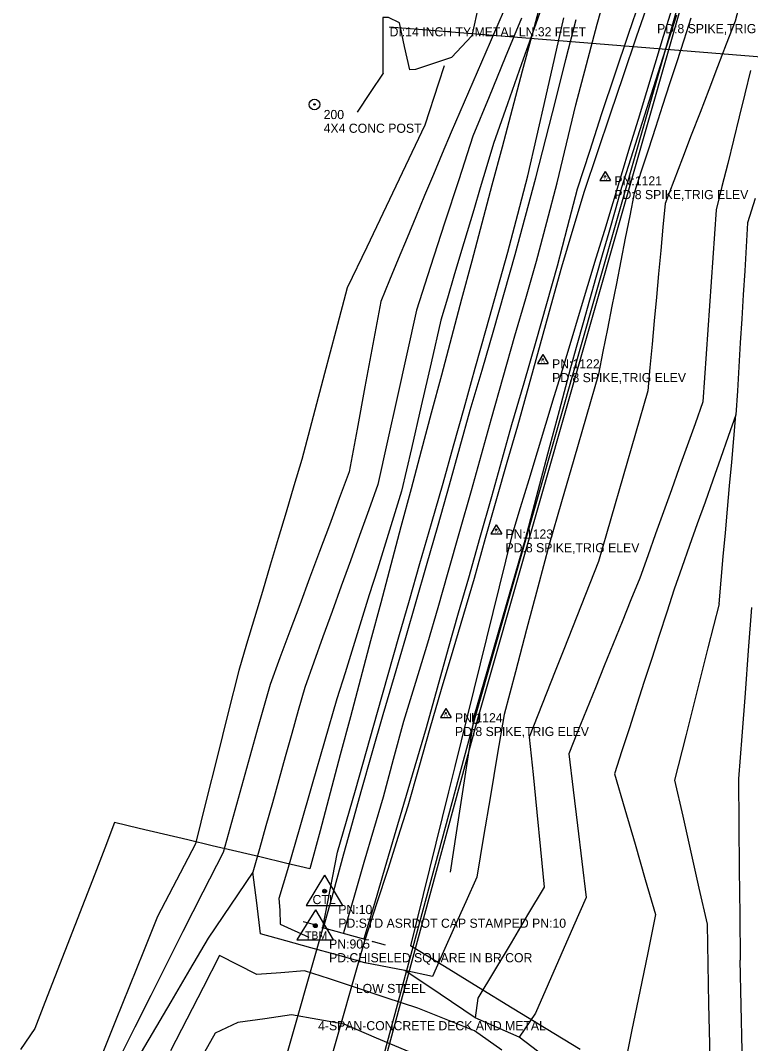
# Model space of a CAD drawing. Extents: x 1445297 to 1476720, y 2042269 to 2057889.
# Drawn here: x 1445937 to 1446336, y 2055534 to 2056093 of the extents above; entities that cross this region are included whole.
import ezdxf

# ---------------------------------------------------------------- set-up
doc = ezdxf.new("R2010")
doc.units = 0
for name, color, linetype in [('S_BRIDGE', 7, 'Continuous'), ('S_DITCHLINE', 7, 'Continuous'), ('S_DRG_PT_SYM', 7, 'Continuous'), ('S_EDGE_PAVEMENT', 7, 'Continuous'), ('S_FIBER_OPTIC_CABLE', 7, 'Continuous'), ('S_IRON_PIN', 7, 'Continuous'), ('S_IRON_PIN_ANNOT', 7, 'Continuous'), ('S_MSC_PT_SYM', 7, 'Continuous'), ('S_PAVEMENT_CROWN', 7, 'Continuous'), ('S_PRIMARY_CTL', 7, 'Continuous'), ('S_PRIMARY_CTL_ANNOT', 7, 'Continuous'), ('S_SECONDARY_CTL', 7, 'Continuous'), ('S_SECONDARY_CTL_ANNOT', 7, 'Continuous'), ('S_SHOULDER', 7, 'Continuous'), ('S_SIDE_DRAIN', 7, 'Continuous'), ('S_SIDE_DRAIN_ANNOT', 7, 'Continuous'), ('S_STR_PT_SYM', 7, 'Continuous'), ('S_STREAM', 7, 'Continuous'), ('S_SURVEY_TEXT_ANNOT', 7, 'Continuous'), ('S_TREE', 7, 'Continuous'), ('S_UNDERGROUND_CABLE', 7, 'Continuous'), ('S_UTL_PT_SYM', 7, 'Continuous'), ('S_WALL', 7, 'Continuous')]:
    doc.layers.add(name, color=color, linetype=linetype)

msp = doc.modelspace()

# ---------------------------------------------------------------- linework, layer by layer
at = {"layer": 'S_BRIDGE'}
for p, q in [((1446101.76, 2055597.5), (1446074.53, 2055501.41)), ((1446124.93, 2055591.15), (1446101.76, 2055597.5)), ((1446097.53, 2055494.89), (1446124.93, 2055591.15))]:
    msp.add_line(p, q, dxfattribs=at)
at = {"layer": 'S_DITCHLINE'}
for points in [[(1446332.26, 2056112.65), (1446327.11, 2056093), (1446322.32, 2056080.54), (1446317.54, 2056068.07), (1446312.75, 2056055.61), (1446307.96, 2056043.15), (1446303.18, 2056030.69), (1446298.39, 2056018.23), (1446293.6, 2056005.77), (1446288.82, 2055993.31), (1446287.64, 2055980.52), (1446286.46, 2055967.72), (1446285.28, 2055954.93), (1446284.1, 2055942.14), (1446282.92, 2055929.34), (1446281.74, 2055916.55), (1446280.56, 2055903.76), (1446279.39, 2055890.96), (1446272.64, 2055867.62), (1446265.9, 2055844.29), (1446259.16, 2055820.95), (1446252.41, 2055797.61), (1446247.69, 2055785.62), (1446242.97, 2055773.63), (1446238.25, 2055761.64), (1446233.53, 2055749.65), (1446228.81, 2055737.67), (1446224.09, 2055725.68), (1446219.37, 2055713.69), (1446214.65, 2055701.7), (1446216.68, 2055681.19), (1446218.71, 2055660.69), (1446220.74, 2055640.18), (1446222.77, 2055619.68), (1446213.71, 2055604.49), (1446204.66, 2055589.31), (1446195.61, 2055574.13), (1446186.56, 2055558.95), (1446185.11, 2055548.2)], [(1446200.32, 2056097.96), (1446190.83, 2056076.09), (1446181.35, 2056054.22), (1446171.87, 2056032.35), (1446167.07, 2056020.79), (1446162.27, 2056009.24), (1446157.47, 2055997.68), (1446152.67, 2055986.12), (1446147.88, 2055974.57), (1446143.08, 2055963.01), (1446138.28, 2055951.45), (1446133.48, 2055939.9), (1446129.16, 2055916.58), (1446124.84, 2055893.27), (1446120.52, 2055869.96), (1446116.2, 2055846.65), (1446110.8, 2055832.13), (1446105.4, 2055817.61), (1446099.99, 2055803.1), (1446094.59, 2055788.58), (1446089.19, 2055774.06), (1446083.79, 2055759.54), (1446078.39, 2055745.02), (1446072.99, 2055730.5), (1446066.56, 2055707.53), (1446060.13, 2055684.55), (1446053.7, 2055661.57), (1446047.27, 2055638.59), (1446036.31, 2055617), (1446025.35, 2055595.4), (1446016.61, 2055577.95), (1446007.88, 2055560.51), (1445999.14, 2055543.07), (1445990.41, 2055525.62)], [(1446210.36, 2056094.7), (1446201.52, 2056073.17), (1446192.67, 2056051.65), (1446183.82, 2056030.13), (1446176.1, 2056006.38), (1446168.39, 2055982.62), (1446160.67, 2055958.87), (1446152.95, 2055935.12), (1446147.68, 2055911.27), (1446142.41, 2055887.43), (1446137.14, 2055863.58), (1446131.87, 2055839.74), (1446126.88, 2055825.87), (1446121.88, 2055812), (1446116.89, 2055798.14), (1446111.9, 2055784.27), (1446106.9, 2055770.4), (1446101.91, 2055756.53), (1446096.92, 2055742.66), (1446091.92, 2055728.8), (1446088.39, 2055716.19), (1446084.86, 2055703.59), (1446081.32, 2055690.98), (1446077.79, 2055678.37), (1446074.26, 2055665.77), (1446070.73, 2055653.16), (1446067.19, 2055640.56), (1446063.66, 2055627.95), (1446051.42, 2055609.88), (1446039.19, 2055591.8), (1446028.98, 2055574.42), (1446018.78, 2055557.05), (1446008.57, 2055539.67), (1445998.37, 2055522.29)], [(1446302.94, 2056094.72), (1446299.07, 2056082.77), (1446295.21, 2056070.82), (1446291.34, 2056058.87), (1446287.47, 2056046.92), (1446283.61, 2056034.97), (1446279.74, 2056023.02), (1446275.87, 2056011.07), (1446272, 2055999.12), (1446269.56, 2055986.74), (1446267.12, 2055974.36), (1446264.68, 2055961.98), (1446262.24, 2055949.6), (1446259.8, 2055937.21), (1446257.36, 2055924.83), (1446254.92, 2055912.45), (1446252.48, 2055900.07), (1446245.73, 2055876.79), (1446238.98, 2055853.51), (1446232.22, 2055830.23), (1446225.47, 2055806.95), (1446219.33, 2055783.75), (1446213.19, 2055760.55), (1446207.05, 2055737.35), (1446200.91, 2055714.15), (1446197.17, 2055691.91), (1446193.43, 2055669.67), (1446189.69, 2055647.43), (1446185.95, 2055625.19), (1446179.89, 2055611.62), (1446173.83, 2055598.06), (1446167.77, 2055584.49), (1446161.71, 2055570.93), (1446146.71, 2055574.12)], [(1446168.1, 2056068.58), (1446165.01, 2056059.09), (1446157.54, 2056036.16), (1446146.96, 2056013.93), (1446136.37, 2055991.71), (1446125.79, 2055969.48), (1446115.2, 2055947.25), (1446108.98, 2055923.82), (1446102.75, 2055900.38), (1446096.53, 2055876.94), (1446090.31, 2055853.51), (1446086, 2055839.07), (1446081.7, 2055824.64), (1446077.39, 2055810.21), (1446073.09, 2055795.78), (1446068.78, 2055781.34), (1446064.48, 2055766.91), (1446060.17, 2055752.48), (1446055.87, 2055738.05), (1446049.95, 2055714.36), (1446044.04, 2055690.68), (1446038.12, 2055667), (1446032.21, 2055643.32), (1446021.87, 2055623.45), (1446011.54, 2055603.58), (1446003.88, 2055584.57), (1445996.23, 2055565.56), (1445988.57, 2055546.55), (1445980.92, 2055527.54)], [(1446335.55, 2056066.14), (1446332.43, 2056053.43), (1446329.31, 2056040.72), (1446326.19, 2056028.02), (1446323.07, 2056015.31), (1446319.95, 2056002.61), (1446316.83, 2055989.9), (1446315.92, 2055976.79), (1446315.01, 2055963.67), (1446314.1, 2055950.55), (1446313.19, 2055937.44), (1446312.28, 2055924.32), (1446311.37, 2055911.2), (1446310.47, 2055898.09), (1446309.56, 2055884.97), (1446305.25, 2055872.93), (1446300.94, 2055860.9), (1446296.63, 2055848.86), (1446292.32, 2055836.82), (1446288.01, 2055824.78), (1446283.7, 2055812.75), (1446279.39, 2055800.71), (1446275.08, 2055788.67), (1446270.21, 2055776.66), (1446265.35, 2055764.64), (1446260.49, 2055752.63), (1446255.63, 2055740.61), (1446250.76, 2055728.6), (1446245.9, 2055716.58), (1446241.04, 2055704.57), (1446236.17, 2055692.55), (1446238.54, 2055672.94), (1446240.91, 2055653.32), (1446243.28, 2055633.71), (1446245.65, 2055614.09), (1446238.77, 2055598.27), (1446231.89, 2055582.44), (1446225, 2055566.61), (1446218.12, 2055550.79), (1446209.18, 2055537.67)], [(1446338.08, 2055996.22), (1446333.95, 2055982.83), (1446333.15, 2055969.71), (1446332.35, 2055956.59), (1446331.55, 2055943.48), (1446330.75, 2055930.36), (1446329.95, 2055917.24), (1446329.16, 2055904.12), (1446328.36, 2055891), (1446327.56, 2055877.89), (1446323.34, 2055865.97), (1446319.12, 2055854.05), (1446314.9, 2055842.13), (1446310.68, 2055830.21), (1446306.46, 2055818.29), (1446302.24, 2055806.38), (1446298.02, 2055794.46), (1446293.8, 2055782.54), (1446289.73, 2055769.92), (1446285.65, 2055757.31), (1446281.58, 2055744.7), (1446277.51, 2055732.08), (1446273.44, 2055719.47), (1446269.37, 2055706.86), (1446265.29, 2055694.25), (1446261.22, 2055681.63), (1446266.83, 2055662.4), (1446272.43, 2055643.17), (1446278.04, 2055623.94), (1446283.64, 2055604.71), (1446279.34, 2055583.7), (1446275.03, 2055562.7), (1446270.72, 2055541.69), (1446266.42, 2055520.69)], [(1446318.36, 2055774.56), (1446319.51, 2055787.47), (1446320.66, 2055800.39), (1446321.81, 2055813.31), (1446322.96, 2055826.22), (1446324.11, 2055839.14), (1446325.26, 2055852.05), (1446326.41, 2055864.97), (1446327.56, 2055877.89)], [(1446318.36, 2055774.56), (1446312.27, 2055750.48), (1446306.19, 2055726.4), (1446300.11, 2055702.32), (1446294.03, 2055678.24), (1446298.47, 2055658.52), (1446302.92, 2055638.8), (1446307.36, 2055619.09), (1446311.81, 2055599.37), (1446312.23, 2055577.56), (1446312.65, 2055555.76), (1446313.08, 2055533.95), (1446313.5, 2055512.14), (1446297.96, 2055497.05), (1446296.61, 2055480.35), (1446295.26, 2055463.64)], [(1446222.88, 2055527.1), (1446209.18, 2055537.67), (1446197.15, 2055542.93), (1446185.11, 2055548.2), (1446165.91, 2055561.16), (1446146.71, 2055574.12), (1446124.74, 2055578.4), (1446109.99, 2055582.42), (1446095.23, 2055586.44), (1446081.53, 2055590.3), (1446067.83, 2055594.16), (1446065.75, 2055611.06), (1446063.66, 2055627.95)], [(1446199.6, 2055530.55), (1446184.71, 2055541.08), (1446169.19, 2055547.32), (1446153.68, 2055553.55), (1446136.41, 2055559.27), (1446119.14, 2055564.99), (1446105.47, 2055569.49), (1446091.81, 2055574), (1446078.82, 2055572.94), (1446065.84, 2055571.88), (1446045.31, 2055582.28), (1446036.43, 2055564.91), (1446027.55, 2055547.55), (1446018.67, 2055530.18)], [(1446148.96, 2055529.68), (1446131.24, 2055537.2), (1446113.52, 2055544.72), (1446099.13, 2055547.27), (1446084.73, 2055549.82), (1446070.08, 2055547.77), (1446055.42, 2055545.72), (1446043.06, 2055539.85), (1446033.86, 2055523.68)]]:
    msp.add_lwpolyline(points, dxfattribs=at)
at = {"layer": 'S_DRG_PT_SYM'}
msp.add_lwpolyline([(1446138.31, 2056089.75), (1446138.31, 2056089.8), (1446138.31, 2056089.75), (1446138.26, 2056089.75), (1446138.31, 2056089.75), (1446138.31, 2056089.7), (1446138.31, 2056089.75), (1446138.36, 2056089.75)], dxfattribs=at)
at = {"layer": 'S_EDGE_PAVEMENT'}
for points in [[(1446124.44, 2055591.62), (1446130.18, 2055611.02), (1446135.93, 2055630.43), (1446141.01, 2055647.71), (1446146.09, 2055665), (1446152.27, 2055685.98), (1446158.46, 2055706.97), (1446164.44, 2055728.63), (1446170.42, 2055750.29), (1446175.98, 2055769.58), (1446181.53, 2055788.86), (1446187.82, 2055811.06), (1446194.1, 2055833.26), (1446199.62, 2055852.95), (1446205.13, 2055872.64), (1446211.78, 2055895.37), (1446218.42, 2055918.09), (1446224.25, 2055938.74), (1446230.07, 2055959.39), (1446235.56, 2055980.37), (1446241.05, 2056001.36), (1446247.68, 2056022), (1446254.32, 2056042.65), (1446261.62, 2056064.35), (1446268.92, 2056086.05), (1446275.15, 2056104.73)], [(1446102.18, 2055597.53), (1446107.75, 2055617.69), (1446113.32, 2055637.84), (1446118.08, 2055654.91), (1446122.84, 2055671.97), (1446128.86, 2055693.02), (1446134.88, 2055714.08), (1446141.04, 2055735.09), (1446147.2, 2055756.1), (1446152.87, 2055775.76), (1446158.53, 2055795.43), (1446164.76, 2055817.54), (1446170.99, 2055839.65), (1446176.7, 2055860.01), (1446182.41, 2055880.36), (1446188.81, 2055902.38), (1446195.2, 2055924.39), (1446201.07, 2055944.99), (1446206.94, 2055965.58), (1446212.55, 2055986.49), (1446218.16, 2056007.4), (1446223.62, 2056028.76), (1446229.08, 2056050.12), (1446234.67, 2056072.06), (1446240.25, 2056094)]]:
    msp.add_lwpolyline(points, dxfattribs=at)
at = {"layer": 'S_FIBER_OPTIC_CABLE'}
for p, q in [((1446319.44, 2056184.59), (1446184.54, 2055711.05)), ((1446184.54, 2055711.05), (1446100.6, 2055399.96))]:
    msp.add_line(p, q, dxfattribs=at)
at = {"layer": 'S_IRON_PIN'}
for radius in [2.91, 0.411, 0.262, 0.212, 0.145, 0.0822, 0.0581]:
    msp.add_circle((1446097.27, 2056047.54), radius, dxfattribs=at)
at = {"layer": 'S_MSC_PT_SYM'}
for points in [[(1446119.87, 2055566.79), (1446119.87, 2055566.84), (1446119.87, 2055566.79), (1446119.82, 2055566.79), (1446119.87, 2055566.79), (1446119.87, 2055566.74), (1446119.87, 2055566.79), (1446119.92, 2055566.79)], [(1446099.24, 2055546.45), (1446099.24, 2055546.5), (1446099.24, 2055546.45), (1446099.19, 2055546.45), (1446099.24, 2055546.45), (1446099.24, 2055546.4), (1446099.24, 2055546.45), (1446099.29, 2055546.45)]]:
    msp.add_lwpolyline(points, dxfattribs=at)
at = {"layer": 'S_PAVEMENT_CROWN'}
msp.add_lwpolyline([(1446113.36, 2055594.97), (1446118.92, 2055614.15), (1446124.48, 2055633.34), (1446129.69, 2055651.19), (1446134.89, 2055669.05), (1446140.48, 2055689.71), (1446146.07, 2055710.37), (1446152.66, 2055731.81), (1446159.25, 2055753.25), (1446164.78, 2055772.59), (1446170.32, 2055791.93), (1446176.66, 2055814.24), (1446183, 2055836.55), (1446188.5, 2055856.26), (1446194, 2055875.96), (1446200.4, 2055898.47), (1446206.79, 2055920.97), (1446212.68, 2055941.44), (1446218.56, 2055961.92), (1446224.22, 2055983.27), (1446229.87, 2056004.61), (1446235, 2056025.97), (1446240.13, 2056047.33), (1446245.97, 2056069.34), (1446251.8, 2056091.35), (1446256.96, 2056110.34)], dxfattribs=at)
at = {"layer": 'S_PRIMARY_CTL'}
for p, q in [((1446102.78, 2055626.18), (1446092.74, 2055609.67)), ((1446102.78, 2055626.18), (1446112.6, 2055609.67)), ((1446097.74, 2055607.32), (1446087.7, 2055590.81)), ((1446092.74, 2055609.67), (1446112.6, 2055609.67)), ((1446097.74, 2055607.32), (1446107.56, 2055590.81)), ((1446087.7, 2055590.81), (1446107.56, 2055590.81))]:
    msp.add_line(p, q, dxfattribs=at)
for centre, radius in [((1446102.78, 2055617.48), 1.04), ((1446102.78, 2055617.48), 0.609), ((1446102.78, 2055617.48), 0.344), ((1446097.74, 2055598.62), 1.04), ((1446097.74, 2055598.62), 0.609), ((1446097.74, 2055598.62), 0.344)]:
    msp.add_circle(centre, radius, dxfattribs=at)
at = {"layer": 'S_SECONDARY_CTL'}
for p, q in [((1446256.14, 2056010.88), (1446253.13, 2056005.92)), ((1446256.14, 2056010.88), (1446259.09, 2056005.92)), ((1446253.13, 2056005.92), (1446259.09, 2056005.92)), ((1446222.08, 2055910.85), (1446219.07, 2055905.9)), ((1446222.08, 2055910.85), (1446225.02, 2055905.9)), ((1446219.07, 2055905.9), (1446225.02, 2055905.9)), ((1446196.63, 2055817.83), (1446193.62, 2055812.88)), ((1446193.62, 2055812.88), (1446199.58, 2055812.88)), ((1446196.63, 2055817.83), (1446199.58, 2055812.88)), ((1446169.05, 2055717.38), (1446166.04, 2055712.42)), ((1446166.04, 2055712.42), (1446172, 2055712.42)), ((1446169.05, 2055717.38), (1446172, 2055712.42))]:
    msp.add_line(p, q, dxfattribs=at)
for centre, radius in [((1446256.14, 2056008.27), 0.311), ((1446256.14, 2056008.27), 0.183), ((1446256.14, 2056008.27), 0.103), ((1446222.08, 2055908.24), 0.311), ((1446222.08, 2055908.24), 0.183), ((1446222.08, 2055908.24), 0.103), ((1446196.63, 2055815.22), 0.311), ((1446196.63, 2055815.22), 0.183), ((1446196.63, 2055815.22), 0.103), ((1446169.05, 2055714.77), 0.311), ((1446169.05, 2055714.77), 0.183), ((1446169.05, 2055714.77), 0.103)]:
    msp.add_circle(centre, radius, dxfattribs=at)
at = {"layer": 'S_SHOULDER'}
for points in [[(1446125.05, 2055591.49), (1446131.39, 2055610.74), (1446137.73, 2055629.99), (1446143.06, 2055647.07), (1446148.4, 2055664.15), (1446154.48, 2055685.33), (1446160.56, 2055706.51), (1446166.76, 2055727.87), (1446172.96, 2055749.23), (1446178.81, 2055768.9), (1446184.65, 2055788.58), (1446190.76, 2055810.37), (1446196.88, 2055832.16), (1446202.62, 2055852.03), (1446208.37, 2055871.9), (1446214.61, 2055894.32), (1446220.86, 2055916.74), (1446226.66, 2055937.78), (1446232.46, 2055958.81), (1446238.63, 2055979.5), (1446244.8, 2056000.2), (1446251.93, 2056021.27), (1446259.05, 2056042.34), (1446266.18, 2056063.41), (1446273.3, 2056084.48), (1446279.78, 2056103.22)], [(1446101.85, 2055597.67), (1446105.89, 2055618.28), (1446109.93, 2055638.89), (1446114.82, 2055655.77), (1446119.72, 2055672.65), (1446125.73, 2055693.96), (1446131.75, 2055715.27), (1446137.55, 2055735.88), (1446143.36, 2055756.49), (1446149.14, 2055776.53), (1446154.92, 2055796.58), (1446161.22, 2055818.53), (1446167.53, 2055840.49), (1446173.27, 2055861), (1446179.02, 2055881.52), (1446185.16, 2055903.35), (1446191.31, 2055925.18), (1446197.1, 2055945.96), (1446202.9, 2055966.75), (1446208.35, 2055987.6), (1446213.81, 2056008.46), (1446218.76, 2056030), (1446223.71, 2056051.55), (1446228.65, 2056073.21), (1446233.59, 2056094.87)]]:
    msp.add_lwpolyline(points, dxfattribs=at)
at = {"layer": 'S_SIDE_DRAIN'}
msp.add_line((1446472.55, 2056062.73), (1446138.31, 2056089.75), dxfattribs=at)
at = {"layer": 'S_STR_PT_SYM'}
for points in [[(1446101.76, 2055597.5), (1446101.76, 2055598), (1446101.76, 2055597.5), (1446101.26, 2055597.5), (1446101.76, 2055597.5), (1446101.76, 2055597), (1446101.76, 2055597.5), (1446102.26, 2055597.5)], [(1446124.93, 2055591.15), (1446124.93, 2055591.65), (1446124.93, 2055591.15), (1446124.43, 2055591.15), (1446124.93, 2055591.15), (1446124.93, 2055590.65), (1446124.93, 2055591.15), (1446125.43, 2055591.15)]]:
    msp.add_lwpolyline(points, dxfattribs=at)
at = {"layer": 'S_STREAM'}
for points in [[(1446239.56, 2056307.57), (1446233.8, 2056285.21), (1446228.05, 2056262.84), (1446222.29, 2056240.48), (1446216.54, 2056218.11), (1446208.39, 2056195.99), (1446200.24, 2056173.86), (1446192.09, 2056151.73), (1446183.94, 2056129.6), (1446188.42, 2056108.64), (1446183.21, 2056085.14), (1446172.21, 2056073.13), (1446152.45, 2056066.59), (1446149.39, 2056066.51), (1446146.53, 2056079.29), (1446143.67, 2056092.08), (1446137.62, 2056095.12), (1446134.69, 2056095.02), (1446134.68, 2056079.99), (1446134.67, 2056064.97), (1446134.81, 2056064.71), (1446127.73, 2056054.02), (1446120.66, 2056043.33)], [(1446225.87, 2056113.4), (1446218.18, 2056091.58), (1446210.48, 2056069.76), (1446202.78, 2056047.94), (1446195.08, 2056026.12), (1446191.48, 2056014.06), (1446187.89, 2056002), (1446184.29, 2055989.93), (1446180.69, 2055977.87), (1446177.09, 2055965.81), (1446173.5, 2055953.74), (1446169.9, 2055941.68), (1446166.3, 2055929.61), (1446160.95, 2055906.23), (1446155.6, 2055882.85), (1446150.25, 2055859.46), (1446144.9, 2055836.08), (1446140.48, 2055821.91), (1446136.06, 2055807.74), (1446131.64, 2055793.56), (1446127.22, 2055779.39), (1446122.81, 2055765.22), (1446118.39, 2055751.05), (1446113.97, 2055736.88), (1446109.55, 2055722.7), (1446102.78, 2055699.32), (1446096.02, 2055675.94), (1446089.25, 2055652.55), (1446082.48, 2055629.17), (1446077.87, 2055613.54), (1446078.32, 2055607.16), (1446078.55, 2055599.43), (1446094.13, 2055592.41)], [(1446295.01, 2056096.28), (1446287.5, 2056072.74), (1446279.99, 2056049.19), (1446272.47, 2056025.65), (1446264.96, 2056002.1), (1446261.49, 2055989.79), (1446258.03, 2055977.48), (1446254.56, 2055965.17), (1446251.09, 2055952.86), (1446247.62, 2055940.54), (1446244.15, 2055928.23), (1446240.68, 2055915.92), (1446237.21, 2055903.61), (1446230.95, 2055880.02), (1446224.68, 2055856.43), (1446218.42, 2055832.84), (1446212.15, 2055809.25), (1446205.25, 2055785.31), (1446198.35, 2055761.36), (1446191.45, 2055737.42), (1446184.55, 2055713.47), (1446181.24, 2055692.09), (1446177.94, 2055670.71), (1446174.64, 2055649.33), (1446171.34, 2055627.95)], [(1446336.12, 2055772.48), (1446334.34, 2055749.08), (1446332.57, 2055725.68), (1446330.8, 2055702.29), (1446329.02, 2055678.89), (1446329.22, 2055654.11), (1446329.42, 2055629.33), (1446329.63, 2055604.55), (1446329.83, 2055579.77)], [(1446331.06, 2055530.16), (1446330.44, 2055554.96), (1446329.83, 2055579.77)]]:
    msp.add_lwpolyline(points, dxfattribs=at)
at = {"layer": 'S_TREE'}
for points in [[(1446221.87, 2056107.32), (1446216.34, 2056086.55), (1446210.81, 2056065.78), (1446205.29, 2056045.01), (1446199.76, 2056024.25), (1446194.23, 2056003.48), (1446188.71, 2055982.71), (1446183.18, 2055961.94), (1446177.65, 2055941.18), (1446172.13, 2055920.41), (1446166.6, 2055899.64), (1446161.07, 2055878.87), (1446155.55, 2055858.11), (1446150.02, 2055837.34), (1446144.49, 2055816.57), (1446138.97, 2055795.8), (1446133.44, 2055775.04), (1446127.91, 2055754.27), (1446122.39, 2055733.5), (1446116.86, 2055712.73), (1446111.33, 2055691.97), (1446105.81, 2055671.2), (1446100.28, 2055650.43), (1446094.75, 2055629.66), (1446081.42, 2055632.83), (1446068.08, 2055635.99), (1446054.74, 2055639.16), (1446041.41, 2055642.32), (1446028.07, 2055645.48), (1446014.74, 2055648.65), (1446001.4, 2055651.81), (1445988.06, 2055654.98), (1445982.61, 2055640.92), (1445977.16, 2055626.86), (1445971.71, 2055612.8), (1445966.26, 2055598.74), (1445960.81, 2055584.68), (1445955.36, 2055570.62), (1445949.9, 2055556.56), (1445944.45, 2055542.5), (1445936.59, 2055530.99)], [(1446292.46, 2056099.86), (1446287.86, 2056084.71), (1446283.27, 2056069.56), (1446278.67, 2056054.41), (1446274.08, 2056039.25), (1446269.48, 2056024.1), (1446264.88, 2056008.95), (1446260.29, 2055993.8), (1446255.69, 2055978.64), (1446251.1, 2055963.49), (1446246.5, 2055948.34), (1446241.9, 2055933.19), (1446237.31, 2055918.04), (1446232.71, 2055902.88), (1446228.12, 2055887.73), (1446223.52, 2055872.58), (1446218.92, 2055857.43), (1446214.33, 2055842.27), (1446209.73, 2055827.12), (1446205.14, 2055811.97), (1446201.68, 2055797.94), (1446198.22, 2055783.92), (1446194.76, 2055769.89), (1446191.3, 2055755.86), (1446187.84, 2055741.84), (1446184.38, 2055727.81), (1446180.92, 2055713.78), (1446177.46, 2055699.76), (1446174, 2055685.73), (1446170.54, 2055671.71), (1446167.08, 2055657.68), (1446163.62, 2055643.65), (1446160.16, 2055629.63), (1446156.7, 2055615.6), (1446153.24, 2055601.57), (1446149.78, 2055587.55)], [(1446242.39, 2055530.99), (1446223.87, 2055542.3), (1446205.34, 2055553.61), (1446186.82, 2055564.92), (1446168.3, 2055576.24), (1446149.78, 2055587.55)]]:
    msp.add_lwpolyline(points, dxfattribs=at)
at = {"layer": 'S_UNDERGROUND_CABLE'}
for p, q in [((1446321.29, 2056184.23), (1446186.26, 2055711.49)), ((1446186.26, 2055711.49), (1446101.82, 2055399.59))]:
    msp.add_line(p, q, dxfattribs=at)
at = {"layer": 'S_UTL_PT_SYM'}
msp.add_lwpolyline([(1446184.54, 2055711.05), (1446184.54, 2055711.1), (1446184.54, 2055711.05), (1446184.49, 2055711.05), (1446184.54, 2055711.05), (1446184.54, 2055711), (1446184.54, 2055711.05), (1446184.59, 2055711.05)], dxfattribs=at)
at = {"layer": 'S_WALL'}
for points in [[(1446098.23, 2055598.9), (1446097.69, 2055598.91), (1446097.38, 2055599.07), (1446091.05, 2055600.74)], [(1446128.6, 2055590.21), (1446128.93, 2055589.99), (1446129.26, 2055590.05), (1446135.81, 2055588.2)]]:
    msp.add_lwpolyline(points, dxfattribs=at)

# ---------------------------------------------------------------- texts
at = {"layer": 'S_IRON_PIN_ANNOT'}
for s, p in [('200', (1446102.27, 2056039.54)), ('4X4 CONC POST', (1446102.27, 2056032.04))]:
    msp.add_text(s, height=5, dxfattribs=at).set_placement(p)
at = {"layer": 'S_PRIMARY_CTL'}
for s, height, p in [('CTL', 5, (1446096.19, 2055610.41)), ('TBM', 4.287, (1446092.08, 2055591.23))]:
    msp.add_text(s, height=height, dxfattribs=at).set_placement(p)
at = {"layer": 'S_PRIMARY_CTL_ANNOT'}
for s, p in [('PN:10', (1446110.28, 2055604.98)), ('PD:STD ASRDOT CAP STAMPED PN:10', (1446110.28, 2055597.48)), ('PN:905', (1446105.24, 2055586.12)), ('PD:CHISELED SQUARE IN BR COR', (1446105.24, 2055578.62))]:
    msp.add_text(s, height=5, dxfattribs=at).set_placement(p)
at = {"layer": 'S_SECONDARY_CTL'}
for p in [(1446254.94, 2056006.26), (1446220.87, 2055906.23), (1446195.43, 2055813.21), (1446167.85, 2055712.75)]:
    msp.add_text('TV', height=1.5, dxfattribs=at).set_placement(p)
at = {"layer": 'S_SECONDARY_CTL_ANNOT'}
for s, p in [('PD:8 SPIKE,TRIG ELEV', (1446284.47, 2056086.5)), ('PN:1121', (1446261.14, 2056003.27)), ('PD:8 SPIKE,TRIG ELEV', (1446261.14, 2055995.77)), ('PN:1122', (1446227.08, 2055903.24)), ('PD:8 SPIKE,TRIG ELEV', (1446227.08, 2055895.74)), ('PN:1123', (1446201.63, 2055810.22)), ('PD:8 SPIKE,TRIG ELEV', (1446201.63, 2055802.72)), ('PN:1124', (1446174.05, 2055709.77)), ('PD:8 SPIKE,TRIG ELEV', (1446174.05, 2055702.27))]:
    msp.add_text(s, height=5, dxfattribs=at).set_placement(p)
at = {"layer": 'S_SIDE_DRAIN_ANNOT'}
msp.add_text('DI:14 INCH TY:METAL LN:32 FEET', height=5, dxfattribs=at).set_placement((1446138.31, 2056084.75))
at = {"layer": 'S_SURVEY_TEXT_ANNOT'}
for s, p in [('LOW STEEL', (1446119.87, 2055561.79)), ('4-SPAN-CONCRETE DECK AND METAL ', (1446099.24, 2055541.45))]:
    msp.add_text(s, height=5, dxfattribs=at).set_placement(p)
at = {"layer": 'S_UTL_PT_SYM'}
msp.add_text('U', height=6, dxfattribs=at).set_placement((1446182.63, 2055708.95))

doc.saveas('drawing.dxf')
